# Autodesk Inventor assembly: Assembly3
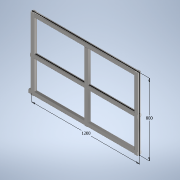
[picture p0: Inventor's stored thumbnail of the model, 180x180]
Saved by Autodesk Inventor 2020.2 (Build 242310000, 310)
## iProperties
_SolveAssemblyDoc: Frame Generator Solve Assembly
_Version: 15.0.0
Created: 2020-01
Part Number: Assembly3
Document SubType Name: Assembly
Designer: thira
Author: thira
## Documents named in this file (3)
- F:\99.โปรแกรมอัดหน้าจอ\Synergysoft\FRAME\Frame_Generator\Frame\Assembly3.iam
- F:\99.โปรแกรมอัดหน้าจอ\Synergysoft\FRAME\Structure.ipt
- F:\99.โปรแกรมอัดหน้าจอ\Synergysoft\FRAME\Frame_Generator\Frame\Assembly3\Frame\Frame 1580197904690.iam
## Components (2 placed, 2 different names)
1. Structure:1
2. Frame 1580197904690:1 [sub-assembly]
